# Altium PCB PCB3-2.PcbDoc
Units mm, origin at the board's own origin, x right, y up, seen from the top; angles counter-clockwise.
Board outline 20 x 20 mm, 2 copper layers (Top Layer, Bottom Layer); 6 components, 14 nets, 39 pads, 2 vias.
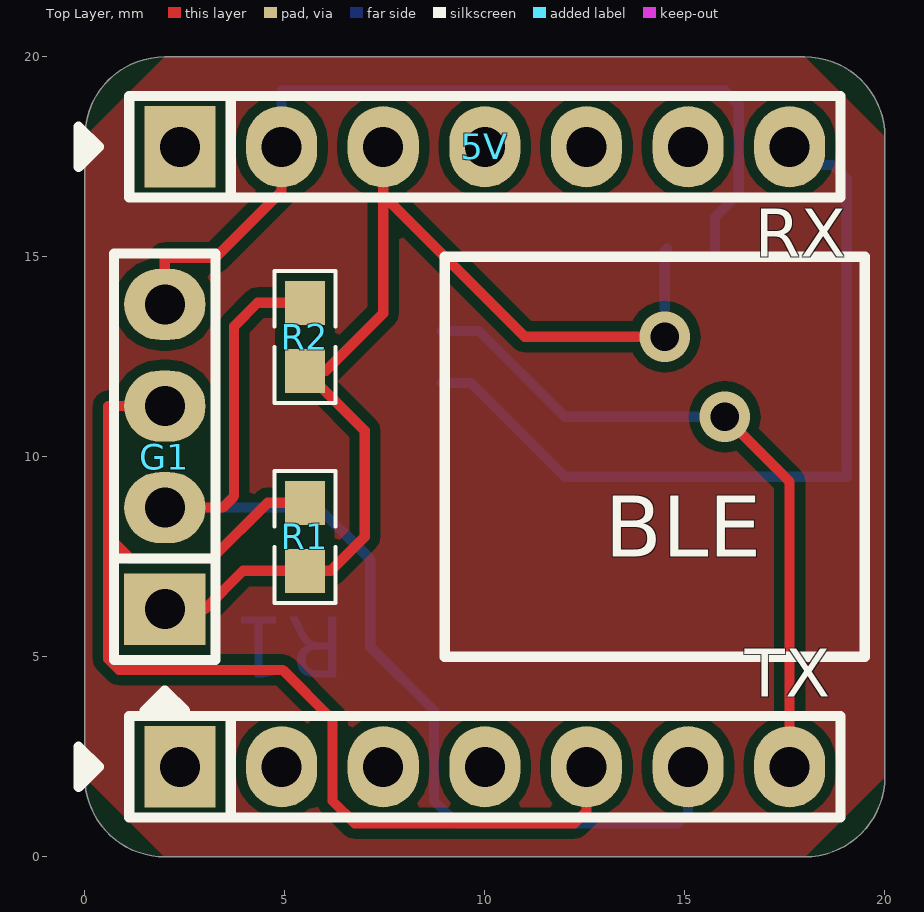
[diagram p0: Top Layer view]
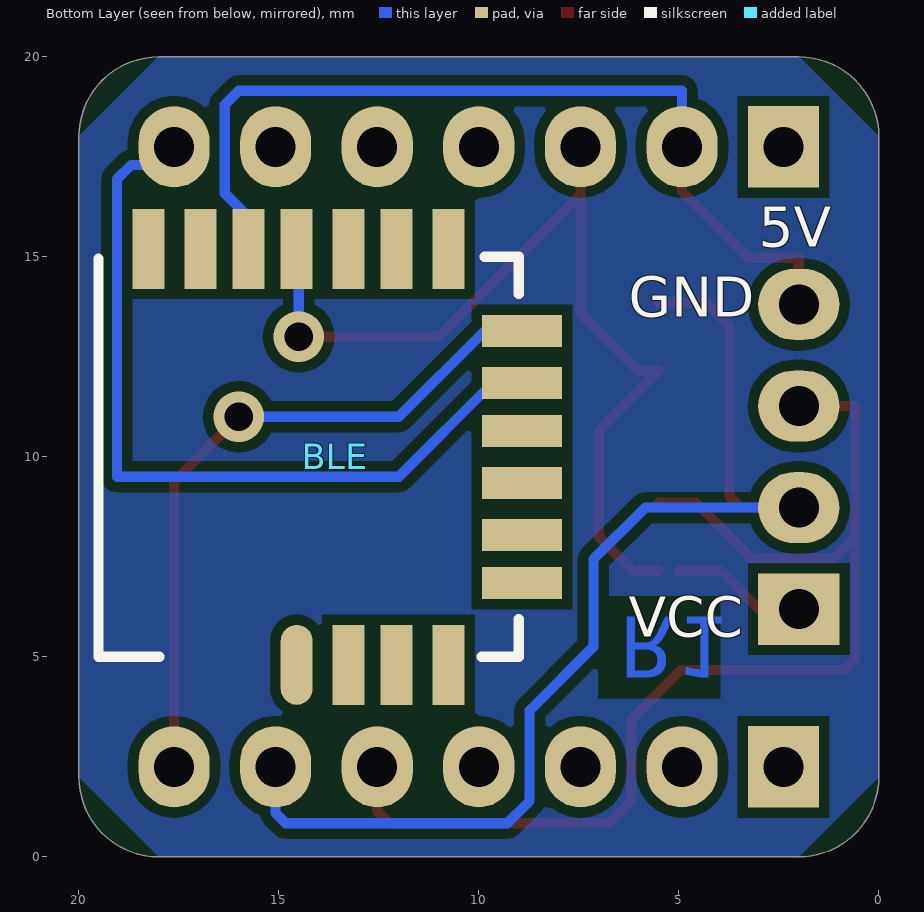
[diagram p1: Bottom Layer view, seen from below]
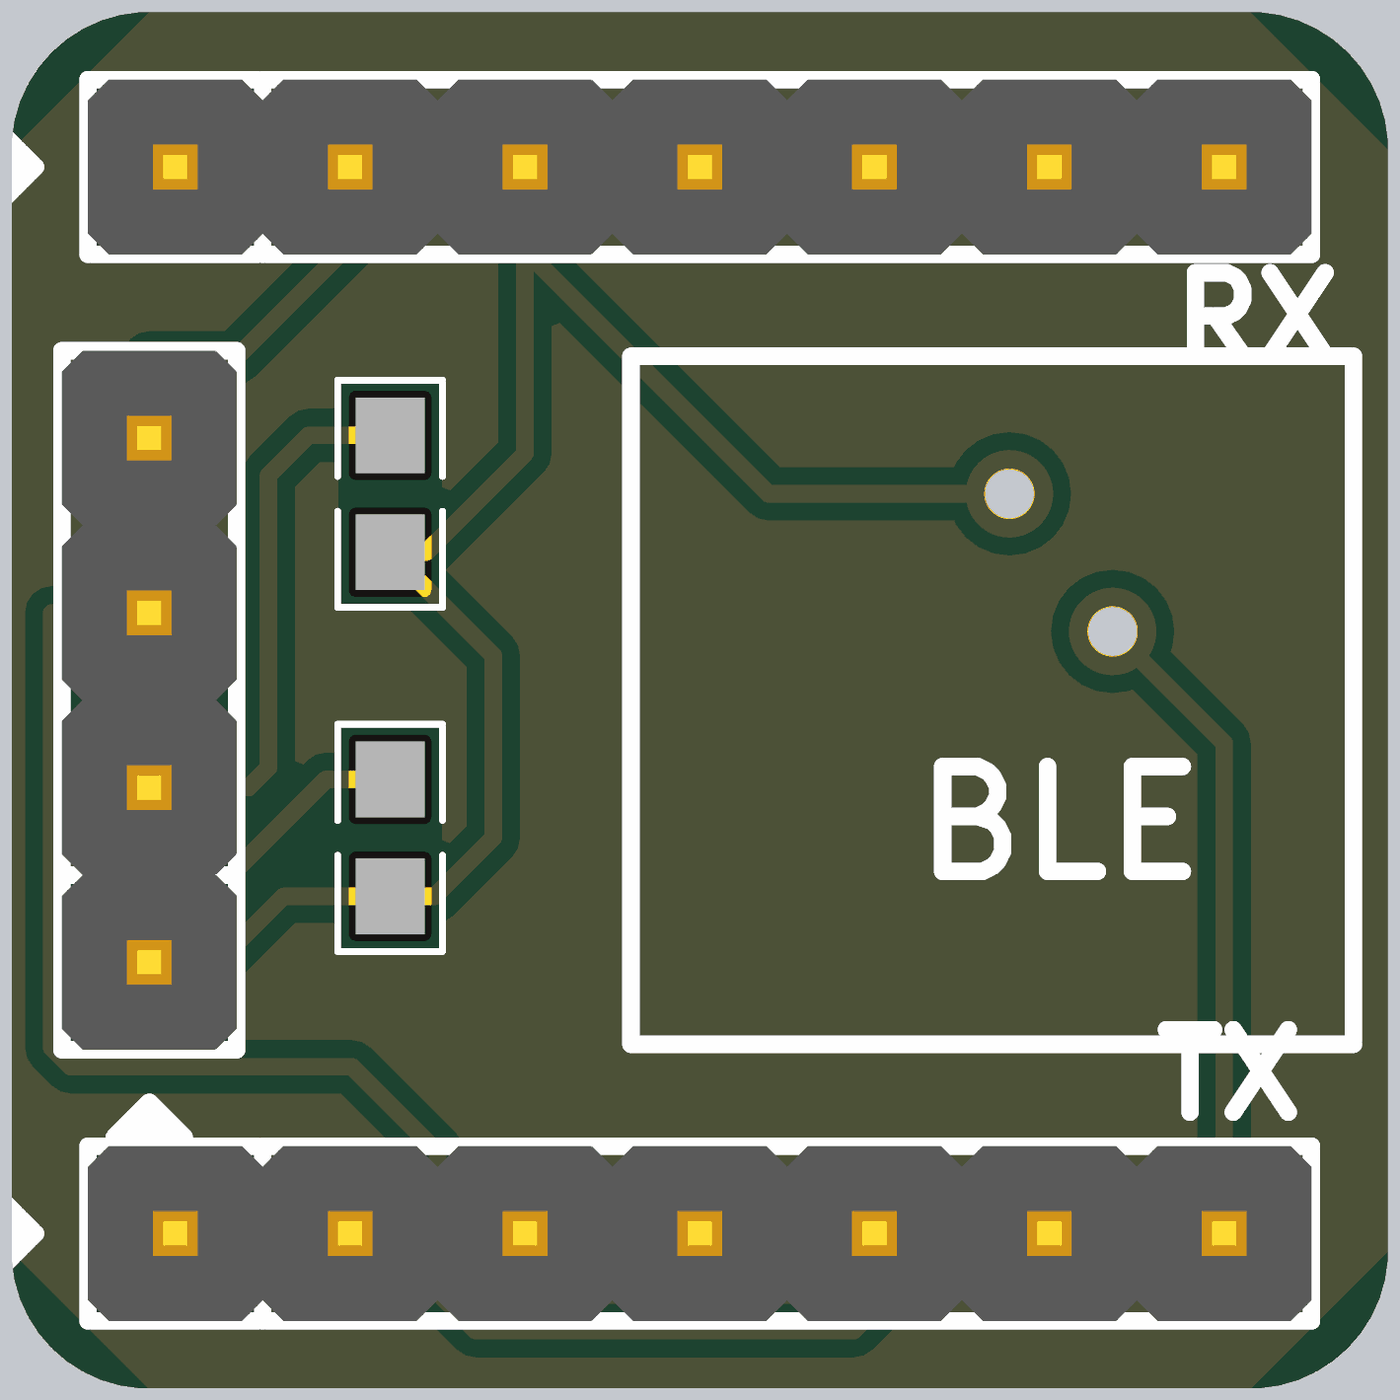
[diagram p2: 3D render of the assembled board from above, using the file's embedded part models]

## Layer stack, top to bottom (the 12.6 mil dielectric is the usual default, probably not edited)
Top Solder: solder mask 0.0102, Solder Resist, Dk 3.5
Top Layer: signal copper 0.0356
Dielectric 1: dielectric 0.32, FR-4, Dk 4.8
Bottom Layer: signal copper 0.0356
Bottom Solder: solder mask 0.0102, Solder Resist, Dk 3.5

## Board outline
0,2 0,18 cw(c2,18) 2,20 18,20 cw(c18,18) 20,18 20,2 cw(c18,2) 18,0 2,0 cw(c2,2)

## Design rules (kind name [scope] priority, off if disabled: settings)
Clearance [All] p1: gap=0.254
PolygonConnect [All] p1: connectstyle=Relief reliefconductorwidth=0.254 reliefentries=4 polygonreliefangle="90 Angle" airgapwidth=0.254
RoutingVias [All] p1: holewidth=0.711 width=1.27 viastyle="Through Hole" minholewidth=0.711 minwidth=1.27 maxholewidth=0.711 maxwidth=1.27
SolderMaskExpansion [All] p1: expansion=0.102
Width [All] p1: maxlimit=0.254 minlimit=0.254 preferedwidth=0.254
29 further rules are at their usual default settings.

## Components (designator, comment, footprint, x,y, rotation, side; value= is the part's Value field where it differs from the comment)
5V "HDR1x7" PIN-7-2.54-1.0 10,17.75 r0 top (schematic designator J2)
BLE "WH-BLE103" PCBComponent_1 9,5 r90 bottom
G1 "HDR1x4" PIN-4-2.54-1.0 2,10 r90 top
R1 "Res1" 0603-1 5.5,8 r270 top
R2 "Res1" 0603-1 5.5,13 r270 top
TX "HDR1x7" PIN-7-2.54-1.0 10,2.25 r0 top (schematic designator J1)

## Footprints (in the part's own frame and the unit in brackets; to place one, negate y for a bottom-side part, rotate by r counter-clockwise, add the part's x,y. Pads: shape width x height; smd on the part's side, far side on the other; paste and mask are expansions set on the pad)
0603-1 [mm] "贴片带丝印"
  rect 1.1x1 smd: 1(-0.85,0) 2(0.85,0)
  silkscreen extent -1.65,-0.76 1.65,0.76, body extent -1.14,-0.38 1.14,0.38, height 1
PCBComponent_1 [mm]
  oval 2x0.8 smd: 1(-0.2,5.554)
  rect 2x0.8 smd: 2(-0.2,4.254) 3(-0.2,3.054) 4(-0.2,1.754) 11(10.2,1.754) 12(10.2,3.054) 13(10.2,4.254) 14(10.2,5.554) 15(10.2,6.754) 16(10.2,7.954) 17(10.2,9.254)
  rect 0.8x2 smd: 5(1.846,-0.082) 6(3.046,-0.082) 7(4.346,-0.082) 8(5.646,-0.082) 9(6.846,-0.082) 10(8.146,-0.082)
  silkscreen extent 0,0 10,10.51
PIN-4-2.54-1.0 [mil] "Pin Header"
  rect 70x80 hole 39.37: 1(-150,0)
  oval 70x80 hole 39.37: 2(-50,0) 3(50,0) 4(150,0)
  silkscreen extent -250,-50 200,50, body extent -200,-50 200,50, height 398
PIN-7-2.54-1.0 [mil] "Pin Header"
  rect 70x80 hole 39.37: 1(-300,0)
  oval 70x80 hole 39.37: 2(-200,0) 3(-100,0) 4(0,0) 5(100,0) 6(200,0) 7(300,0)
  silkscreen extent -400,-50 350,50, body extent -350,-50 350,50, height 398

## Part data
5V G1 TX: "Connector"
R1 R2: "贴片电阻"

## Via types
v1: diameter 1.27, hole 0.711, Top Layer to Bottom Layer, tented both sides, 2 vias

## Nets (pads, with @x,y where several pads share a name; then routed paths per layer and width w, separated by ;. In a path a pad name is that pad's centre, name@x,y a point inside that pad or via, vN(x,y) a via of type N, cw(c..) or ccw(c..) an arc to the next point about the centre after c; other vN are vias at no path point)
3.3V: 5V.3 BLE.14 G1.1 R1.2 R2.2 | length 30.5
  Top Layer w0.254: G1.1 2.995,6.19 3.955,7.15 R1.2@5,7.15 ; R1.2 6.15,7.15 7,8 7,10.65 R2.2 6.022,12.15 7.46,13.588 7.46,14.711 ; v1(14.5,13) 11,13 7.46,16.54 ; 7.46,14.711 5V.3 7.46,16.54 ; 7.46,14.711 7.46,16.54
  Bottom Layer w0.254: v1(14.5,13) 14.5,15.146 BLE.14
5V: 5V.1
D0: TX.1
D1: TX.2
D2: TX.3
D3: TX.4
D8: 5V.6
D9: 5V.5
D10: 5V.4
GND: 5V.2 BLE.15 G1.4 | length 22.7
  Top Layer w0.254: G1.4 2,14.976 3.26,14.976 4.92,16.636 5V.2
  Bottom Layer w0.254: 5V.2 4.92,19.151 16,19.151 16.35,18.801 16.35,16.585 15.754,15.989 BLE.15
RX: 5V.7 BLE.9 | length 20.6
  Bottom Layer w0.254: BLE.9 9.657,11.846 12.002,9.5 19.048,9.5 19.048,16.941 18.692,17.296 17.62,17.296 5V.7
SCL: G1.2 R2.1 TX.6 | length 28.3
  Top Layer w0.254: G1.2 3.446,8.73 3.732,9.016 3.732,13.266 4.316,13.85 R2.1
  Bottom Layer w0.254: G1.2 5.84,8.73 7.135,7.435 7.135,5.252 8.73,3.657 8.73,1.396 9.289,0.837 14.826,0.837 15.08,1.091 TX.6
SDA: G1.3 R1.1 TX.5 | length 29.5
  Top Layer w0.254: G1.3 0.582,11.27 0.582,8 ; R1.1 4.57,8.85 3.18,7.46 1.122,7.46 0.582,8 ; TX.5 12.54,1.142 12.235,0.837 6.749,0.837 6.19,1.396 6.19,3.428 4.945,4.673 0.862,4.673 0.582,4.952 0.582,8
TX: BLE.10 TX.7 | length 17.4
  Top Layer w0.254: v1(16,11) 17.62,9.38 TX.7
  Bottom Layer w0.254: BLE.10 9.854,13.146 12,11 v1(16,11)
pads on no net: BLE.1 BLE.2 BLE.3 BLE.4 BLE.5 BLE.6 BLE.7 BLE.8 BLE.11 BLE.12 BLE.13 BLE.16 BLE.17

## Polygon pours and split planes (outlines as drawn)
no net on Top Layer "Top Layer-No Net" (solid, pour order 4): 0,18 2,20 2,20.01 17.99,20.01 18,20 20,18 20,2.01 20.01,2 18.01,0 18,0 2.01,0 2,-0.01 -0.01,2 -0.01,18
no net on Bottom Layer "Top Layer-No Net" (solid, pour order 6): -0.01,18 1.99,20 2,20 17.99,20 18,20.01 20,18.01 20,18 20,2 18,0 2.01,0 2,-0.01 -0.01,2 -0.01,18

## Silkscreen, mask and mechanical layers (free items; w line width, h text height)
Top Overlay:
  lines w0.254: 9,5 9,15 19.5,15 19.5,5 9,5
  text "RX" at 16.75,15 h1.2
Bottom Overlay:
  text "GND" at 6.25,13.5 h1
  text "VCC" at 6.25,5.5 h1
Mechanical 1:
  lines w0.254: 0,2 ccw(c2,2) 2,0 18,0 ccw(c18,2) 20,2 20,18 ccw(c18,18) 18,20 14,20 2,20 ccw(c2,18) 0,18 0,2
